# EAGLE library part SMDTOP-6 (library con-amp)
AMP connector
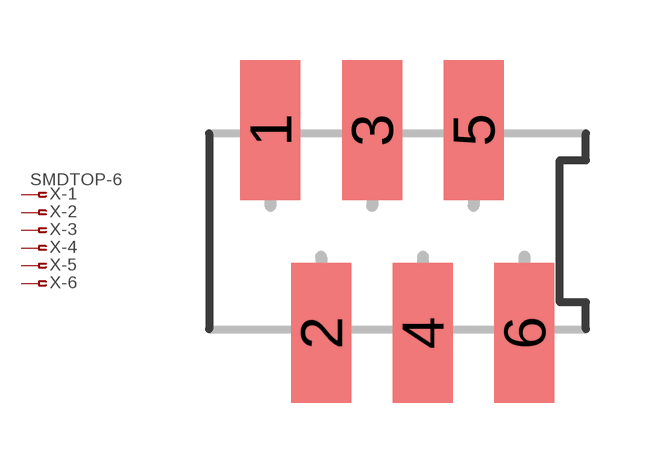
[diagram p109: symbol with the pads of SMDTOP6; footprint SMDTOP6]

Designator prefix X; gates -1=PIN-FV -2=PIN-F -3=PIN-F -4=PIN-F -5=PIN-F -6=PIN-F

## SMDTOP-6 (OC_FARNELL: unknown; OC_NEWARK: unknown)  [SMDTOP6]
1  -1:1  pas
2  -2:1  pas
3  -3:1  pas
4  -4:1  pas
5  -5:1  pas
6  -6:1  pas

## Footprint SMDTOP6 (pad centres in mm)
AMP connector
smd 1.5 x 3.5: 1 -3.175,2.54; 2 -1.905,-2.54; 3 -0.635,2.54; 4 0.635,-2.54; 5 1.905,2.54; 6 3.175,-2.54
